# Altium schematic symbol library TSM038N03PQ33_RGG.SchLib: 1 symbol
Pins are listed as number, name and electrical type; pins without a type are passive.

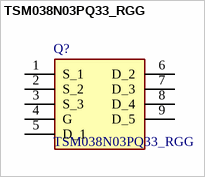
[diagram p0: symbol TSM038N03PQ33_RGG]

## TSM038N03PQ33_RGG
designator Q?
MOSFET Power MOSFET, N-CHAN 30V, 80A, 3.8mOhm; Manufacturer_Name: Taiwan Semiconductor; Manufacturer_Part_Number: TSM038N03PQ33 RGG; Geometry.Height: 0.8mm
footprint TSM038N03PQ33RGG
pins: 1 S_1, 2 S_2, 3 S_3, 4 G, 5 D_1, 6 D_2, 7 D_3, 8 D_4, 9 D_5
